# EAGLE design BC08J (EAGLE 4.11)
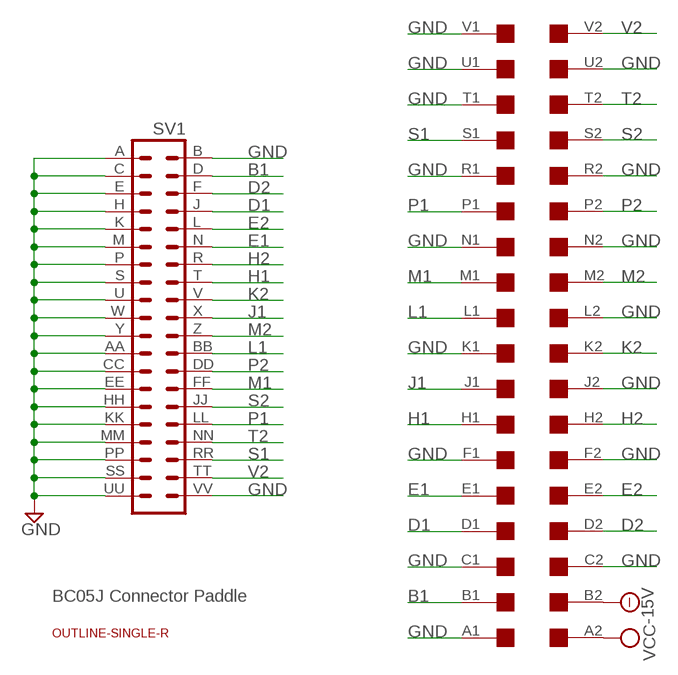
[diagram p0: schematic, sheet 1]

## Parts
SV1  DEC40PIN  [DEC40PIN]
U$1  SINGLE  [EDGE-CON2]
U$2  OUTLINE-SINGLE-R  [SINGLE-R]

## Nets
-15V: U$1.B2
B1: SV1.D U$1.B1
D1: SV1.J U$1.D1
D2: SV1.F U$1.D2
E1: SV1.N U$1.E1
E2: SV1.L U$1.E2
GND: SV1.A SV1.AA SV1.B SV1.C SV1.CC SV1.E SV1.EE SV1.H SV1.HH SV1.K SV1.KK SV1.M SV1.MM SV1.P SV1.PP SV1.S SV1.SS SV1.U SV1.UU SV1.VV SV1.W SV1.Y U$1.A1 U$1.C1 U$1.C2 U$1.F1 U$1.F2 U$1.J2 U$1.K1 U$1.L2 U$1.N1 U$1.N2 U$1.R1 U$1.R2 U$1.T1 U$1.U1 U$1.U2 U$1.V1
H1: SV1.T U$1.H1
H2: SV1.R U$1.H2
J1: SV1.X U$1.J1
K2: SV1.V U$1.K2
L1: SV1.BB U$1.L1
M1: SV1.FF U$1.M1
M2: SV1.Z U$1.M2
P1: SV1.LL U$1.P1
P2: SV1.DD U$1.P2
S1: SV1.RR U$1.S1
S2: SV1.JJ U$1.S2
T2: SV1.NN U$1.T2
V2: SV1.TT U$1.V2
VCC: U$1.A2

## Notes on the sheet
- BC05J Connector Paddle

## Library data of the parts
SV1 = dec-con:DEC40PIN: PIN HEADER
U$1 = dec-con:SINGLE: Double-Height DEC board
U$2 = dec-con:OUTLINE-*: Board outlines for DEC boards.

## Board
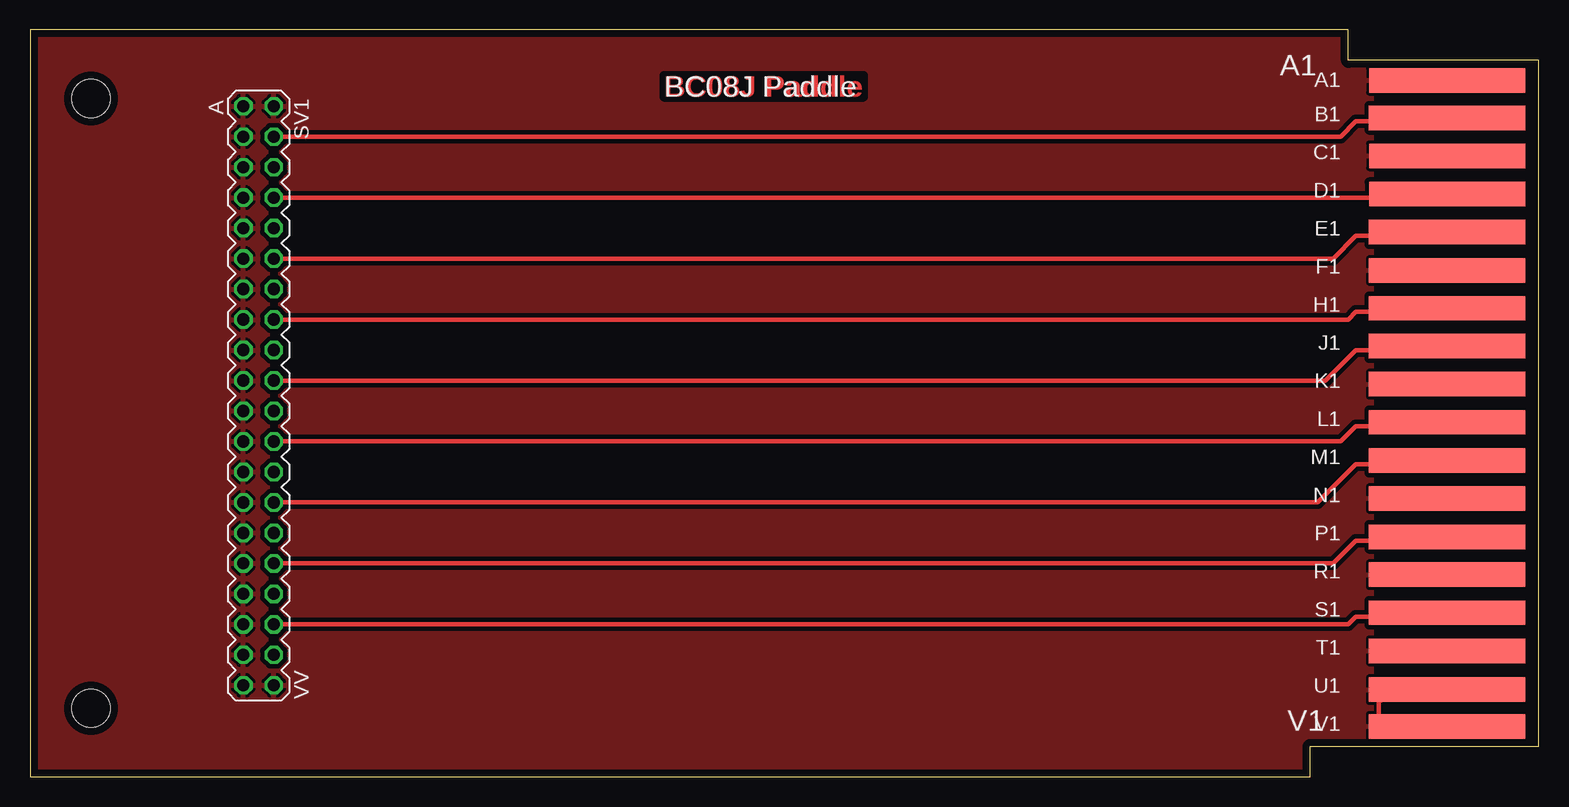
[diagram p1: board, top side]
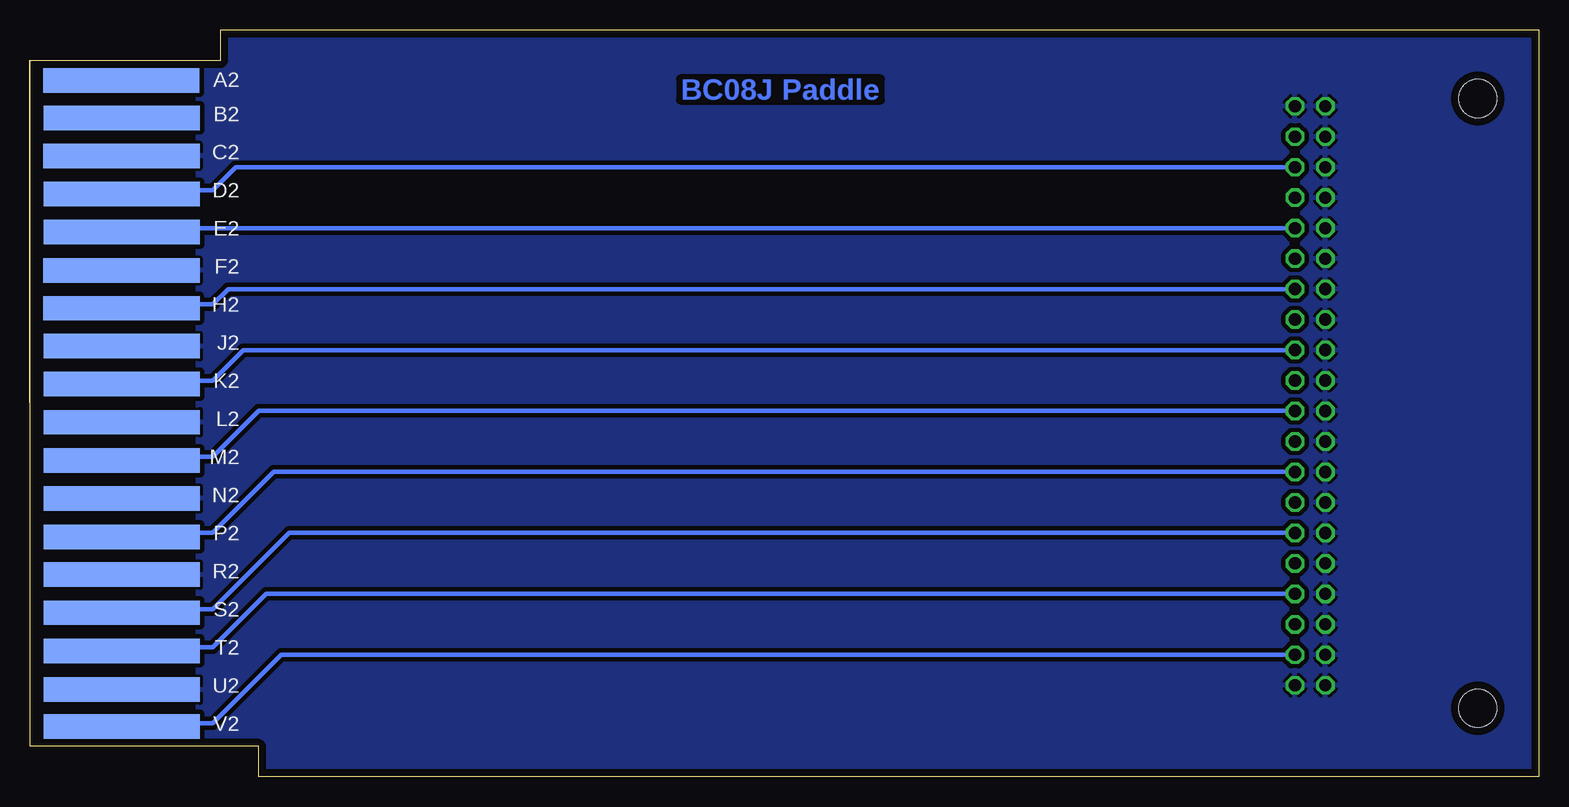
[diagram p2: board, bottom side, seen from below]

Size 125.73 x 62.23 mm. Coordinates in mm from the lower left corner, seen from the top.
Copper layers (1*16): Top 0.035mm / dielectric 1.5mm / Bottom 0.035mm
Design rules "olimex10mil": minimum track width 15mil, minimum drill 24mil, track to track 15mil, track to pad 10mil, pad to pad 10mil, via to via 10mil, smd to smd 10mil, copper to edge 25mil, drill to drill 10mil, minimum pad ring 10mil, minimum via ring 8mil, stop-mask expansion 0mil, vias tented up to drill 0mil, thermal gap 10mil

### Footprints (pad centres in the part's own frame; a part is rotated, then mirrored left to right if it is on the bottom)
DEC40PIN = drill 1.016 octagon: A -24.13,-1.27; AA 3.81,-1.27; B -24.13,1.27; BB 3.81,1.27; C -21.59,-1.27; CC 6.35,-1.27; D -21.59,1.27; DD 6.35,1.27; E -19.05,-1.27; EE 8.89,-1.27; F -19.05,1.27; FF 8.89,1.27; H -16.51,-1.27; HH 11.43,-1.27; J -16.51,1.27; JJ 11.43,1.27; K -13.97,-1.27; KK 13.97,-1.27; L -13.97,1.27; LL 13.97,1.27; M -11.43,-1.27; MM 16.51,-1.27; N -11.43,1.27; NN 16.51,1.27; P -8.89,-1.27; PP 19.05,-1.27; R -8.89,1.27; RR 19.05,1.27; S -6.35,-1.27; SS 21.59,-1.27; T -6.35,1.27; TT 21.59,1.27; U -3.81,-1.27; UU 24.13,-1.27; V -3.81,1.27; VV 24.13,1.27; W -1.27,-1.27; X -1.27,1.27; Y 1.27,-1.27; Z 1.27,1.27
EDGE-CON2 = smd 13.017 x 2.032: A1 7.633,4.207; B1 7.639,7.327; C1 7.636,10.489; D1 7.633,13.665; E1 7.642,16.84; F1 7.642,20.041; H1 7.642,23.19; J1 7.642,26.34; K1 7.642,29.515; L1 7.642,32.69; M1 7.642,35.89; N1 7.642,39.04; P1 7.642,42.24; R1 7.642,45.39; S1 7.642,48.565; T1 7.642,51.74; U1 7.642,54.966; V1 7.642,58.026 | smd 13.017 x 2.032 bottom: A2 7.614,4.207; B2 7.642,7.328; C2 7.617,10.49; D2 7.642,13.665; E2 7.642,16.84; F2 7.617,20.041; H2 7.617,23.19; J2 7.642,26.34; K2 7.642,29.515; L2 7.642,32.69; M2 7.642,35.89; N2 7.642,39.04; P2 7.642,42.24; R2 7.642,45.39; S2 7.642,48.565; T2 7.642,51.74; U2 7.642,54.966; V2 7.642,58.026
SINGLE-R = hole 3.175: 5.08,5.715; 5.08,56.515

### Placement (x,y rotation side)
SV1  19.05,31.75 270 top
U$1  125.73,62.23 180 top
U$2  0,0 0 top

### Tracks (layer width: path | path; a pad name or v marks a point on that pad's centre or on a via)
B1
  Top 0.381: SV1.D 20.95,53.34 109.22,53.34 110.49,54.61 111.76,54.61 U$1.B1
D1
  Top 0.381: SV1.J 20.95,48.26 111.76,48.26 U$1.D1
D2
  Bottom 0.381: SV1.F 20.95,50.8 108.58,50.8 110.49,48.9 111.76,48.9 U$1.D2
E1
  Top 0.381: SV1.N 20.95,43.18 108.58,43.18 110.49,45.09 111.76,45.09 U$1.E1
E2
  Bottom 0.381: SV1.L 20.95,45.72 111.76,45.72 U$1.E2
GND
  Top 0.381: 111.76,4 111.76,3.81 U$1.V1 112.39,5.08 112.39,6.35 U$1.U1 | U$1.T1 111.76,10.16 111.76,10.29 | U$1.R1 111.76,16.51 111.76,16.64 | U$1.N1 111.76,22.86 111.76,22.99 | U$1.K1 111.76,32.38 111.76,32.51 | U$1.F1 111.76,41.91 111.76,41.99 | U$1.C1 111.76,51.44 111.76,51.55 | U$1.A1 111.76,57.78 111.76,57.82
  Bottom 0.381: U$1.U1 111.76,6.99 111.76,7.06 | U$1.R1 111.76,16.51 111.76,16.64 | U$1.N1 111.76,22.86 111.76,22.99 | U$1.L2 111.76,29.21 111.76,29.34 | U$1.J2 111.76,35.56 111.76,35.69 | U$1.F2 111.76,41.91 111.76,41.99 | U$1.C2 111.76,51.44 111.76,51.54
  pour Top (isolate 0.305): 111.76,0 0,0 0,62.23 111.76,62.23
  pour Bottom (isolate 0.305): 111.76,0 0,0 0,62.23 111.76,62.23
H1
  Top 0.381: SV1.T 20.95,38.1 109.86,38.1 110.49,38.73 111.76,38.73 U$1.H1
H2
  Bottom 0.381: SV1.R 20.95,40.64 109.22,40.64 110.49,39.37 111.76,39.37 U$1.H2
J1
  Top 0.381: SV1.X 20.95,33.02 107.95,33.02 110.49,35.56 111.76,35.56 U$1.J1
K2
  Bottom 0.381: SV1.V 20.95,35.56 107.95,35.56 110.49,33.02 111.76,33.02 U$1.K2
L1
  Top 0.381: SV1.BB 20.95,27.94 109.22,27.94 110.49,29.21 111.76,29.21 U$1.L1
M1
  Top 0.381: SV1.FF 20.95,22.86 107.31,22.86 110.49,26.04 111.76,26.04 U$1.M1
M2
  Bottom 0.381: SV1.Z 20.95,30.48 106.68,30.48 110.49,26.67 111.76,26.67 U$1.M2
P1
  Top 0.381: SV1.LL 20.95,17.78 108.58,17.78 110.49,19.68 111.76,19.68 U$1.P1
P2
  Bottom 0.381: SV1.DD 20.95,25.4 105.41,25.4 110.49,20.32 111.76,20.32 U$1.P2
S1
  Top 0.381: SV1.RR 20.95,12.7 109.86,12.7 110.49,13.34 111.76,13.34 U$1.S1
S2
  Bottom 0.381: SV1.JJ 20.95,20.32 104.14,20.32 110.49,13.97 111.76,13.97 U$1.S2
T2
  Bottom 0.381: SV1.NN 20.95,15.24 106.05,15.24 110.49,10.79 111.76,10.79 U$1.T2
V2
  Bottom 0.381: SV1.TT 20.95,10.16 104.78,10.16 110.49,4.45 111.76,4.45 U$1.V2

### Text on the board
Top: BC08J Paddle
Bottom: BC08J Paddle
tPlace: BC08J Paddle
tNames: A1 | V1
